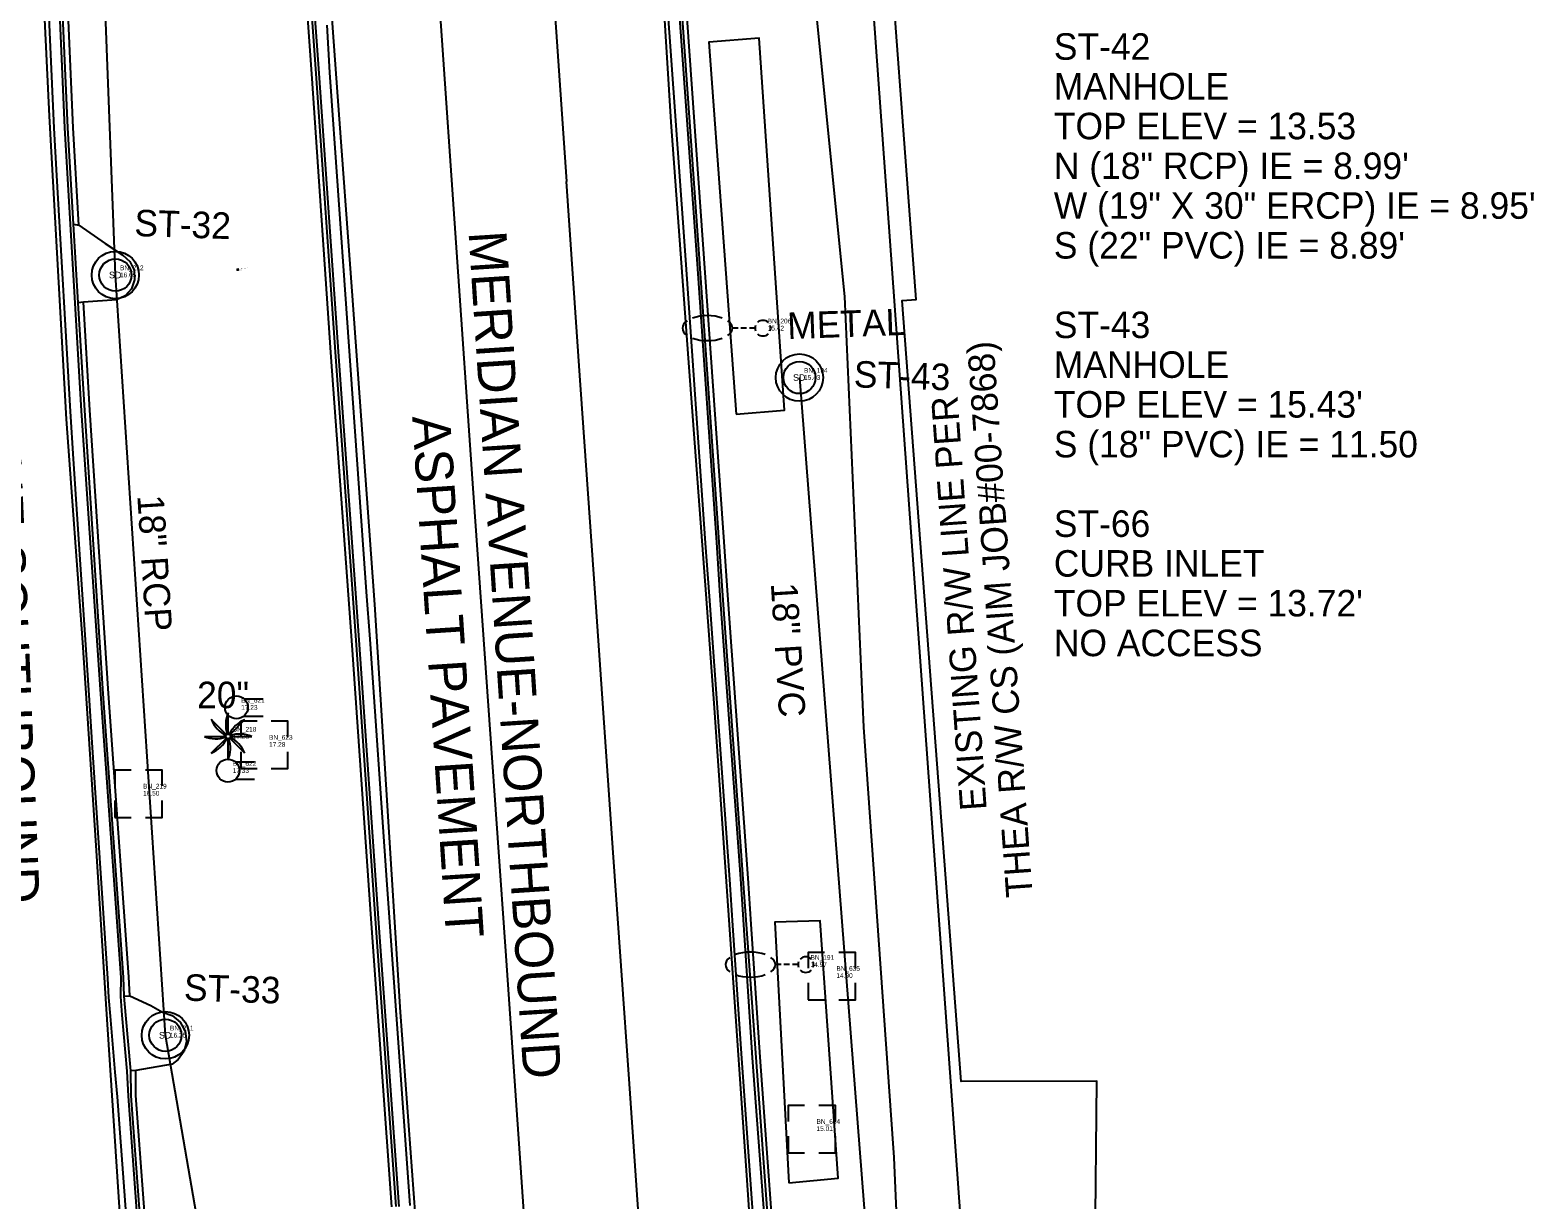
# Model space of a CAD drawing. Extents: x 509744 to 512285, y 1314862 to 1316822.
# Drawn here: x 511177.3 to 511336.2, y 1315382.6 to 1315506.2 of the extents above; entities that cross this region are included whole.
import ezdxf

# ---------------------------------------------------------------- set-up
doc = ezdxf.new("R2010")
doc.units = 0
for name, color, linetype in [('Building_ep', 7, 'Continuous'), ('CGBack_ep', 7, 'Continuous'), ('CGep_ep', 7, 'Continuous'), ('CGFace_ep', 7, 'Continuous'), ('FloodLight_ep', 7, 'Continuous'), ('GroundShot_ep', 7, 'Continuous'), ('InletCurb_ep', 7, 'Continuous'), ('Luminaire_ep', 7, 'Continuous'), ('ManholeSW_ep', 7, 'Continuous'), ('NonPlottingEle_dp', 7, 'Continuous'), ('PavtAsphalt_ep', 7, 'Continuous'), ('PavtBrick_ep', 7, 'Continuous'), ('PipeCulvert_ep', 7, 'Continuous'), ('PMRK_ep', 7, 'Continuous'), ('PullBox_ep', 7, 'Continuous'), ('RWLine_ep', 7, 'Continuous'), ('Slopes_ep', 7, 'Continuous'), ('TextElevLabel', 7, 'Continuous'), ('TextNotes', 7, 'Continuous'), ('TextPtLabel', 7, 'Continuous'), ('TextTopoLabel_ep', 7, 'Continuous'), ('TextUtilLabel_ep', 7, 'Continuous'), ('TreePalm_ep', 7, 'Continuous')]:
    doc.layers.add(name, color=color, linetype=linetype)

msp = doc.modelspace()

# ---------------------------------------------------------------- linework, layer by layer
at = {"layer": 'Building_ep'}
msp.add_lwpolyline([(511313.25, 1315341.71), (511289.5, 1315341.91), (511290.04, 1315395.14), (511275.71, 1315395.11), (511269.48, 1315477.6), (511270.95, 1315477.72), (511267.4, 1315525.27)], dxfattribs=at)
at = {"layer": 'CGBack_ep'}
for points in [[(511283.66, 1315320.87), (511278.26, 1315321.97), (511272.69, 1315324.51), (511270.02, 1315326.63), (511266.38, 1315330.09), (511263.29, 1315334.02), (511260.86, 1315338.1), (511259.34, 1315342.94), (511258.44, 1315347.86), (511257.65, 1315352.8), (511257.34, 1315357.8), (511256.95, 1315362.8), (511256.63, 1315367.8), (511254.47, 1315397.69), (511253.52, 1315411.72), (511253.19, 1315416.58), (511251.05, 1315446.49), (511250.66, 1315452.11), (511248.55, 1315482.03), (511246.42, 1315511.96), (511244.35, 1315541.88), (511243.07, 1315560.3), (511242.79, 1315565.27), (511242.88, 1315571.45)], [(511182.46, 1315485.56), (511181.86, 1315495.85), (511180.54, 1315525.84), (511179.7, 1315549.3), (511179.58, 1315552.11)], [(511204.88, 1315531.49), (511207.03, 1315501.56), (511209.1, 1315471.64), (511211.25, 1315441.71), (511213.34, 1315411.79), (511215.49, 1315381.87)], [(511187.83, 1315404.18), (511187.73, 1315406.17), (511185.57, 1315436.1), (511183.6, 1315466.03), (511182.93, 1315477.45)], [(511198.86, 1315329.69), (511197.19, 1315334.75), (511191.68, 1315353.98), (511191.07, 1315358.73), (511188.48, 1315393.64), (511188.49, 1315396.27)]]:
    msp.add_lwpolyline(points, dxfattribs=at)
at = {"layer": 'CGep_ep'}
for points in [[(511255.91, 1315367.7), (511253.66, 1315397.63), (511252.73, 1315411.67), (511252.4, 1315416.52), (511250.24, 1315446.44), (511249.88, 1315452.06), (511247.8, 1315481.99), (511245.64, 1315511.91), (511243.57, 1315541.84), (511242.29, 1315560.26), (511242.01, 1315565.32), (511242.01, 1315571.49)], [(511205.63, 1315531.54), (511207.8, 1315501.62), (511209.88, 1315471.69), (511212.03, 1315441.77), (511214.11, 1315411.84), (511216.27, 1315381.92)], [(511190.25, 1315358.68), (511187.69, 1315393.58), (511187.55, 1315396.2), (511187.04, 1315402.11), (511186.88, 1315404.1), (511186.93, 1315406.11), (511184.78, 1315436.03), (511182.75, 1315465.97), (511180.98, 1315495.84), (511179.66, 1315525.83)]]:
    msp.add_lwpolyline(points, dxfattribs=at)
at = {"layer": 'CGFace_ep'}
for points in [[(511283.54, 1315320.46), (511278.14, 1315321.56), (511272.57, 1315324.1), (511269.7, 1315326.35), (511266.06, 1315329.81), (511262.97, 1315333.74), (511260.44, 1315338.04), (511258.92, 1315342.88), (511258.03, 1315347.8), (511257.23, 1315352.74), (511256.92, 1315357.74), (511256.53, 1315362.74), (511256.21, 1315367.74), (511254.03, 1315397.66), (511253, 1315411.69), (511252.66, 1315416.54), (511250.5, 1315446.46), (511250.11, 1315452.08), (511248.04, 1315482), (511245.93, 1315511.93), (511243.85, 1315541.85), (511242.57, 1315560.27), (511242.29, 1315565.3), (511242.29, 1315571.48)], [(511181.9, 1315485.68), (511181.3, 1315495.85), (511179.96, 1315525.83), (511179.24, 1315549.3), (511179.15, 1315552.11)], [(511205.35, 1315531.52), (511207.49, 1315501.6), (511209.57, 1315471.67), (511211.72, 1315441.75), (511213.8, 1315411.82), (511215.96, 1315381.9)], [(511187.26, 1315404.13), (511187.16, 1315406.13), (511185.04, 1315436.05), (511183.07, 1315465.99), (511182.39, 1315477.38)], [(511198.37, 1315329.54), (511196.7, 1315334.61), (511191.18, 1315353.83), (511190.55, 1315358.7), (511187.98, 1315393.6), (511187.93, 1315396.23)]]:
    msp.add_lwpolyline(points, dxfattribs=at)
at = {"layer": 'FloodLight_ep'}
for p, q in [((511199.9, 1315435.55), (511201.92, 1315435.55)), ((511199.9, 1315433.71), (511201.92, 1315433.71)), ((511198.99, 1315428.88), (511201.01, 1315428.88)), ((511198.99, 1315427.04), (511201.01, 1315427.04))]:
    msp.add_line(p, q, dxfattribs=at)
for centre in [(511199.11, 1315434.63), (511198.21, 1315427.96)]:
    msp.add_circle(centre, 1.21, dxfattribs=at)
at = {"layer": 'GroundShot_ep'}
for p, q in [((511199.24, 1315480.73), (511199.24, 1315480.98)), ((511199.37, 1315480.86), (511199.12, 1315480.86))]:
    msp.add_line(p, q, dxfattribs=at)
at = {"layer": 'InletCurb_ep'}
for p, q in [((511181.9, 1315485.68), (511182.46, 1315485.56)), ((511182.93, 1315477.45), (511182.39, 1315477.38)), ((511186.45, 1315477.68), (511182.93, 1315477.45))]:
    msp.add_line(p, q, dxfattribs=at)
for points in [[(511182.39, 1315477.38), (511181.9, 1315485.68)], [(511182.46, 1315485.56), (511185.22, 1315483.62), (511187.1, 1315482.4)], [(511187.1, 1315482.4), (511187.85, 1315481.73), (511188.29, 1315480.82), (511188.35, 1315479.81), (511188.01, 1315478.86), (511187.34, 1315478.1), (511186.45, 1315477.68)], [(511192.32, 1315396.95), (511188.49, 1315396.27), (511187.93, 1315396.23), (511187.42, 1315402.14), (511187.26, 1315404.13), (511187.83, 1315404.18)], [(511187.83, 1315404.18), (511190.06, 1315403.13), (511191.31, 1315402.43)], [(511191.31, 1315402.43), (511192.33, 1315402.08), (511193.16, 1315401.38), (511193.68, 1315400.44), (511193.82, 1315399.36), (511193.57, 1315398.31), (511192.95, 1315397.43), (511192.32, 1315396.95)]]:
    msp.add_lwpolyline(points, dxfattribs=at)
at = {"layer": 'Luminaire_ep'}
for p, q in [((511252.12, 1315474.69), (511251.52, 1315474.69)), ((511253.02, 1315474.69), (511252.42, 1315474.69)), ((511253.92, 1315474.69), (511253.32, 1315474.69)), ((511256.66, 1315407.47), (511256.06, 1315407.47)), ((511257.56, 1315407.47), (511256.96, 1315407.47)), ((511258.46, 1315407.47), (511257.86, 1315407.47))]:
    msp.add_line(p, q, dxfattribs=at)
for centre, start, end in [((511254.75, 1315474.69), 159.9115, 200.0885), ((511254.75, 1315474.69), 45, 135), ((511254.75, 1315474.69), 339.9115, 20.0885), ((511254.75, 1315474.69), 225, 315), ((511259.28, 1315407.47), 45, 135), ((511259.28, 1315407.47), 159.9115, 200.0885), ((511259.28, 1315407.47), 225, 315), ((511259.28, 1315407.47), 339.9115, 20.0885)]:
    msp.add_arc(centre, 0.825, start, end, dxfattribs=at)
for centre, start_param, end_param in [((511248.88, 1315474.69), 5.668326, 6.898045), ((511248.88, 1315474.69), 4.075781, 5.348997), ((511248.88, 1315474.69), 2.526733, 3.756452), ((511248.88, 1315474.69), 0.934187, 2.207405), ((511253.42, 1315407.47), 5.668326, 6.898045), ((511253.42, 1315407.47), 4.075781, 5.348997), ((511253.42, 1315407.47), 2.526733, 3.756452), ((511253.42, 1315407.47), 0.934187, 2.207405)]:
    msp.add_ellipse(centre, major_axis=(-2.64, 0), ratio=0.5, start_param=start_param, end_param=end_param, dxfattribs=at)
at = {"layer": 'ManholeSW_ep'}
for centre, radius in [((511186.31, 1315480.3), 2.5), ((511186.31, 1315480.3), 1.7), ((511258.61, 1315469.47), 2.5), ((511258.61, 1315469.47), 1.7), ((511191.6, 1315400), 2.5), ((511191.6, 1315400), 1.7)]:
    msp.add_circle(centre, radius, dxfattribs=at)
at = {"layer": 'PavtAsphalt_ep'}
for points in [[(511254.68, 1315367.53), (511252.51, 1315397.54), (511251.58, 1315411.58), (511251.25, 1315416.44), (511249.09, 1315446.37), (511248.69, 1315451.99), (511246.61, 1315481.91), (511244.45, 1315511.84), (511242.38, 1315541.77), (511241.1, 1315560.18), (511240.82, 1315565.38), (511240.8, 1315571.56)], [(511189.1, 1315358.6), (511187.27, 1315383.53), (511186.54, 1315393.49), (511186.29, 1315396.1), (511185.79, 1315402.01), (511185.63, 1315404), (511185.53, 1315406), (511183.86, 1315430.94), (511183.53, 1315435.93), (511181.89, 1315460.88), (511181.56, 1315465.87), (511180.13, 1315490.83), (511179.84, 1315495.83), (511178.72, 1315520.81)], [(511208.65, 1315506.7), (511208.96, 1315501.71), (511210.69, 1315476.77), (511211.04, 1315471.78), (511212.83, 1315446.84), (511213.19, 1315441.85), (511214.93, 1315416.91), (511215.27, 1315411.93), (511217.07, 1315386.99), (511217.43, 1315382.01)]]:
    msp.add_lwpolyline(points, dxfattribs=at)
at = {"layer": 'PavtBrick_ep'}
for points in [[(511251.91, 1315465.6), (511257.02, 1315466.01), (511254.35, 1315505.32), (511249.03, 1315504.89)], [(511257.49, 1315384.43), (511262.69, 1315384.92), (511260.79, 1315412.1), (511255.99, 1315411.94)]]:
    msp.add_lwpolyline(points, close=True, dxfattribs=at)
at = {"layer": 'PipeCulvert_ep'}
for p, q in [((511186.31, 1315480.3), (511183.52, 1315554.98)), ((511191.6, 1315400), (511186.31, 1315480.3)), ((511258.61, 1315469.47), (511267.16, 1315359.89)), ((511204.45, 1315326.14), (511191.6, 1315400))]:
    msp.add_line(p, q, dxfattribs=at)
at = {"layer": 'PMRK_ep'}
for points in [[(511209.31, 1315234.71), (511207.26, 1315265.11), (511204.06, 1315302.16), (511201.01, 1315314.28), (511193.69, 1315336.6), (511189.8, 1315350.72), (511188.42, 1315358.33), (511187.07, 1315377.02), (511185.39, 1315402.76), (511184.27, 1315420.03), (511182.87, 1315441.48), (511181.16, 1315465.08), (511179.35, 1315497.09), (511177.85, 1315528.55), (511176.89, 1315561.22)], [(511229.18, 1315558.89), (511230.93, 1315533.95), (511232.67, 1315509.01), (511233.98, 1315490.19)], [(511240.68, 1315559.35), (511242.53, 1315534.42), (511243.24, 1315524.81), (511244.8, 1315499.86), (511245.01, 1315496.46), (511246.86, 1315471.53), (511248.71, 1315446.6), (511249.61, 1315434.57), (511251.32, 1315409.63), (511253.04, 1315384.69), (511253.75, 1315374.31), (511255.25, 1315355.97), (511256.35, 1315342.41), (511257.31, 1315338.55), (511257.5, 1315337.78), (511259.12, 1315334.96)], [(511205.56, 1315557.19), (511207.57, 1315529.67), (511209.79, 1315499.17), (511211.29, 1315478.61), (511213.71, 1315445.49), (511216.4, 1315402.44), (511218.86, 1315368.91), (511222.01, 1315324.94), (511224.53, 1315288.59), (511228, 1315238.71), (511228.17, 1315236.36)], [(511217.1, 1315558.03), (511218.85, 1315533.09), (511220.59, 1315508.15), (511222.33, 1315483.21), (511224.07, 1315458.27), (511225.82, 1315433.33), (511227.56, 1315408.39), (511229.3, 1315383.46), (511231.04, 1315358.52), (511232.09, 1315343.56)], [(511244.12, 1315344.98), (511242.38, 1315369.92), (511240.64, 1315394.86), (511238.9, 1315419.8), (511237.16, 1315444.74), (511235.41, 1315469.68), (511233.98, 1315490.19)]]:
    msp.add_lwpolyline(points, dxfattribs=at)
at = {"layer": 'PullBox_ep'}
for points in [[(511201.29, 1315433.17), (511199.56, 1315433.17), (511199.56, 1315431.5)], [(511204.55, 1315431.5), (511204.55, 1315433.17), (511202.79, 1315433.17)], [(511199.56, 1315429.94), (511199.56, 1315428.17)], [(511202.79, 1315428.17), (511204.55, 1315428.17), (511204.55, 1315429.94)], [(511187.99, 1315428.01), (511186.26, 1315428.01), (511186.26, 1315426.34)], [(511191.25, 1315426.34), (511191.25, 1315428.01), (511189.49, 1315428.01)], [(511199.56, 1315428.17), (511201.29, 1315428.17)], [(511186.26, 1315424.79), (511186.26, 1315423.01)], [(511189.49, 1315423.01), (511191.25, 1315423.01), (511191.25, 1315424.79)], [(511186.26, 1315423.01), (511187.99, 1315423.01)], [(511261.26, 1315408.76), (511259.53, 1315408.76), (511259.53, 1315407.08)], [(511264.52, 1315407.08), (511264.52, 1315408.76), (511262.76, 1315408.76)], [(511259.53, 1315405.53), (511259.53, 1315403.76)], [(511262.76, 1315403.76), (511264.52, 1315403.76), (511264.52, 1315405.53)], [(511259.53, 1315403.76), (511261.26, 1315403.76)], [(511259.15, 1315392.59), (511257.42, 1315392.59), (511257.42, 1315390.91)], [(511262.41, 1315390.91), (511262.41, 1315392.59), (511260.65, 1315392.59)], [(511257.42, 1315389.36), (511257.42, 1315387.59)], [(511260.65, 1315387.59), (511262.41, 1315387.59), (511262.41, 1315389.36)], [(511257.42, 1315387.59), (511259.15, 1315387.59)]]:
    msp.add_lwpolyline(points, dxfattribs=at)
at = {"layer": 'RWLine_ep'}
msp.add_line((511278.76, 1315337.37), (511261.23, 1315580.31), dxfattribs=at)
at = {"layer": 'Slopes_ep'}
msp.add_lwpolyline([(511307.12, 1315332.14), (511283.06, 1315336.54), (511273.7, 1315345.72), (511269.92, 1315357.22), (511268.63, 1315387.08), (511265.4, 1315432.53), (511263.39, 1315478.03), (511259.99, 1315512.19), (511255.38, 1315552.32), (511254.62, 1315569.99), (511253.19, 1315580.1), (511262.52, 1315585.27), (511268.86, 1315587.2), (511280.73, 1315589.96), (511302.82, 1315589.29)], dxfattribs=at)
at = {"layer": 'TreePalm_ep'}
for p, q in [((511198.04, 1315431.75), (511196.45, 1315433.34)), ((511198.22, 1315431.82), (511198.22, 1315434.07)), ((511198.4, 1315431.75), (511199.99, 1315433.34)), ((511195.72, 1315431.57), (511197.97, 1315431.57)), ((511196.45, 1315429.8), (511198.04, 1315431.39)), ((511198.22, 1315429.07), (511198.22, 1315431.32)), ((511199.99, 1315429.8), (511198.4, 1315431.39)), ((511198.47, 1315431.57), (511200.72, 1315431.57))]:
    msp.add_line(p, q, dxfattribs=at)
msp.add_circle((511198.22, 1315431.57), 0.25, dxfattribs=at)
for centre, start, end in [((511199.46, 1315434.58), 202.3801, 243.2114), ((511201.22, 1315432.82), 157.3801, 198.2114), ((511201.23, 1315430.33), 112.3801, 153.2114), ((511199.47, 1315428.57), 67.3801, 108.2114), ((511196.97, 1315434.57), 247.3801, 288.2114), ((511195.21, 1315432.81), 292.3801, 333.2114), ((511195.22, 1315430.32), 337.3801, 18.2114), ((511196.98, 1315428.57), 22.3801, 63.2114)]:
    msp.add_arc(centre, 3.25, start, end, dxfattribs=at)

# ---------------------------------------------------------------- texts
at = {"layer": 'ManholeSW_ep'}
for p in [(511185.64, 1315479.95), (511257.93, 1315469.12), (511190.92, 1315399.65)]:
    msp.add_text('SD', height=0.7, dxfattribs=at).set_placement(p)
at = {"layer": 'NonPlottingEle_dp'}
for s, p in [('ST-42', (511285.49, 1315503.04)), ('MANHOLE', (511285.49, 1315498.84)), ('TOP ELEV = 13.53', (511285.49, 1315494.64)), ('N (18" RCP) IE = 8.99\'', (511285.49, 1315490.44)), ('W (19" X 30" ERCP) IE = 8.95\'', (511285.49, 1315486.24)), ('S (22" PVC) IE = 8.89\'', (511285.49, 1315482.04)), ('ST-43', (511285.49, 1315473.64)), ('MANHOLE', (511285.49, 1315469.44)), ("TOP ELEV = 15.43'", (511285.49, 1315465.24)), ('S (18" PVC) IE = 11.50', (511285.49, 1315461.04)), ('ST-66', (511285.49, 1315452.64)), ('CURB INLET', (511285.49, 1315448.44)), ("TOP ELEV = 13.72'", (511285.49, 1315444.24)), ('NO ACCESS', (511285.49, 1315440.04))]:
    msp.add_text(s, height=2.8, dxfattribs=at).set_placement(p)
for s, rotation, p in [('ST-32', 358.1578, (511188.29, 1315484.42)), ('ST-43', 358.1578, (511264.32, 1315468.44)), ('18" RCP', 273.588, (511188.63, 1315456.99)), ('18" PVC', 273.588, (511255.58, 1315447.72)), ('ST-33', 358.1578, (511193.53, 1315403.67))]:
    msp.add_text(s, height=2.8, rotation=rotation, dxfattribs=at).set_placement(p)
at = {"layer": 'TextElevLabel'}
for s, height, p in [('16.97', 0.1, (511199.34, 1315480.81)), ('16.65', 0.5, (511186.8, 1315480.06)), ('15.42', 0.5, (511255.25, 1315474.44)), ('15.43', 0.5, (511259.09, 1315469.23)), ('17.23', 0.5, (511199.61, 1315434.38)), ('17.23', 0.5, (511198.72, 1315431.32)), ('17.28', 0.5, (511202.55, 1315430.47)), ('17.33', 0.5, (511198.71, 1315427.71)), ('16.50', 0.5, (511189.24, 1315425.31)), ('14.97', 0.5, (511259.78, 1315407.22)), ('14.90', 0.5, (511262.51, 1315406.06)), ('16.25', 0.5, (511192.08, 1315399.76)), ('15.01', 0.5, (511260.41, 1315389.89))]:
    msp.add_text(s, height=height, dxfattribs=at).set_placement(p)
at = {"layer": 'TextNotes'}
for s, p in [('THEA R/W CS (AIM JOB#00-7868)', (511283.26, 1315414.66)), ('EXISTING R/W LINE PER', (511278.4, 1315423.83))]:
    msp.add_text(s, height=2.8, rotation=94.0425, dxfattribs=at).set_placement(p)
at = {"layer": 'TextPtLabel'}
for s, height, p in [('BN_212', 0.5, (511186.8, 1315480.81)), ('DEFAULT_836', 0.1, (511199.34, 1315480.96)), ('BN_206', 0.5, (511255.25, 1315475.19)), ('BN_194', 0.5, (511259.09, 1315469.98)), ('BN_621', 0.5, (511199.61, 1315435.13)), ('BN_218', 0.5, (511198.72, 1315432.07)), ('BN_623', 0.5, (511202.55, 1315431.22)), ('BN_622', 0.5, (511198.71, 1315428.46)), ('BN_219', 0.5, (511189.24, 1315426.06)), ('BN_191', 0.5, (511259.78, 1315407.97)), ('BN_635', 0.5, (511262.51, 1315406.81)), ('BN_211', 0.5, (511192.08, 1315400.51)), ('BN_634', 0.5, (511260.41, 1315390.64))]:
    msp.add_text(s, height=height, dxfattribs=at).set_placement(p)
at = {"layer": 'TextTopoLabel_ep'}
for s, rotation, p in [('MERIDIAN AVENUE-SOUTHBOUND', 272.3886, (511170.61, 1315503.21)), ('MERIDIAN AVENUE-NORTHBOUND', 273.7243, (511223.63, 1315484.84)), ('ASPHALT PAVEMENT', 273.7243, (511217.68, 1315465.35))]:
    msp.add_text(s, height=4, rotation=rotation, dxfattribs=at).set_placement(p)
msp.add_text('20"', height=2.8, dxfattribs=at).set_placement((511194.95, 1315434.55))
at = {"layer": 'TextUtilLabel_ep'}
msp.add_text('METAL', height=2.8, rotation=2.0368, dxfattribs=at).set_placement((511257.37, 1315473.53))

doc.saveas('drawing.dxf')
